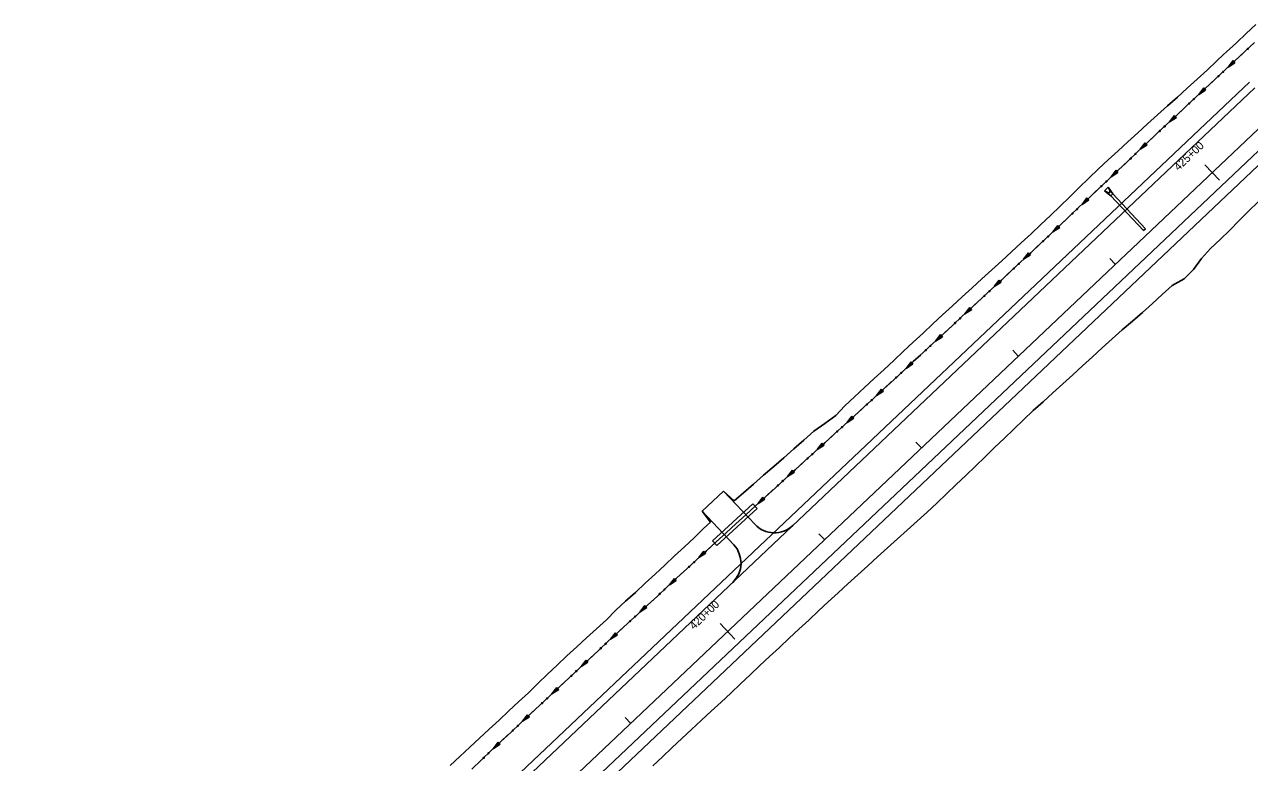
# Model space of a CAD drawing. Extents: x 1375694 to 1433473, y 1931050 to 1967991.
# Drawn here: x 1429493 to 1430411, y 1964646 to 1965198 of the extents above; entities that cross this region are included whole.
import ezdxf

# ---------------------------------------------------------------- set-up
doc = ezdxf.new("R2010")
doc.units = 0
for name, color, linetype in [('62', 7, 'Continuous'), ('R_Drainage', 7, 'Continuous'), ('R_Horz Alg', 7, 'Continuous'), ('R_Horz Alg Annot', 7, 'Continuous'), ('R_Proposed Const Limits', 7, 'Continuous'), ('R_Proposed Road', 7, 'Continuous')]:
    doc.layers.add(name, color=color, linetype=linetype)

msp = doc.modelspace()

# ---------------------------------------------------------------- linework, layer by layer
at = {"layer": '62'}
for p, q in [((1430398.79, 1965171.29), (1430395.12, 1965166.43)), ((1430400.23, 1965169.75), (1430398.79, 1965171.29)), ((1430395.12, 1965166.43), (1430400.23, 1965169.75)), ((1430376.82, 1965150.81), (1430373.16, 1965145.94)), ((1430373.16, 1965145.94), (1430378.26, 1965149.26)), ((1430378.26, 1965149.26), (1430376.82, 1965150.81)), ((1430354.87, 1965130.3), (1430351.21, 1965125.44)), ((1430351.21, 1965125.44), (1430356.31, 1965128.76)), ((1430356.31, 1965128.76), (1430354.87, 1965130.3)), ((1430332.95, 1965109.76), (1430329.32, 1965104.86)), ((1430329.32, 1965104.86), (1430334.4, 1965108.22)), ((1430334.4, 1965108.22), (1430332.95, 1965109.76)), ((1430311.13, 1965089.11), (1430307.5, 1965084.22)), ((1430312.58, 1965087.57), (1430311.13, 1965089.11)), ((1430307.5, 1965084.22), (1430312.58, 1965087.57)), ((1430289.3, 1965068.48), (1430285.67, 1965063.59)), ((1430285.67, 1965063.59), (1430290.75, 1965066.94)), ((1430290.75, 1965066.94), (1430289.3, 1965068.48)), ((1430267.48, 1965047.84), (1430263.83, 1965042.96)), ((1430263.83, 1965042.96), (1430268.93, 1965046.3)), ((1430268.93, 1965046.3), (1430267.48, 1965047.84)), ((1430245.54, 1965027.33), (1430241.87, 1965022.46)), ((1430241.87, 1965022.46), (1430246.98, 1965025.78)), ((1430246.98, 1965025.78), (1430245.54, 1965027.33)), ((1430223.57, 1965006.85), (1430219.89, 1965002)), ((1430225.01, 1965005.3), (1430223.57, 1965006.85)), ((1430219.89, 1965002), (1430225.01, 1965005.3)), ((1430201.54, 1964986.43), (1430197.86, 1964981.57)), ((1430197.86, 1964981.57), (1430202.98, 1964984.88)), ((1430202.98, 1964984.88), (1430201.54, 1964986.43)), ((1430179.51, 1964966.01), (1430175.82, 1964961.16)), ((1430175.82, 1964961.16), (1430180.95, 1964964.46)), ((1430180.95, 1964964.46), (1430179.51, 1964966.01)), ((1430157.46, 1964945.61), (1430153.77, 1964940.76)), ((1430153.77, 1964940.76), (1430158.9, 1964944.06)), ((1430158.9, 1964944.06), (1430157.46, 1964945.61)), ((1430135.37, 1964925.27), (1430131.66, 1964920.43)), ((1430131.66, 1964920.43), (1430136.8, 1964923.71)), ((1430136.8, 1964923.71), (1430135.37, 1964925.27)), ((1430113.24, 1964904.96), (1430109.51, 1964900.14)), ((1430114.67, 1964903.39), (1430113.24, 1964904.96)), ((1430109.51, 1964900.14), (1430114.67, 1964903.39)), ((1430090.99, 1964884.78), (1430087.26, 1964879.97)), ((1430087.26, 1964879.97), (1430092.41, 1964883.21)), ((1430092.41, 1964883.21), (1430090.99, 1964884.78)), ((1430068.75, 1964864.59), (1430065.02, 1964859.77)), ((1430065.02, 1964859.77), (1430070.17, 1964863.02)), ((1430070.17, 1964863.02), (1430068.75, 1964864.59)), ((1430046.53, 1964844.38), (1430042.8, 1964839.56)), ((1430042.8, 1964839.56), (1430047.95, 1964842.82)), ((1430047.95, 1964842.82), (1430046.53, 1964844.38)), ((1430002.21, 1964803.81), (1429998.52, 1964798.96)), ((1430003.64, 1964802.25), (1430002.21, 1964803.81)), ((1429998.52, 1964798.96), (1430003.64, 1964802.25)), ((1429980.14, 1964783.44), (1429976.45, 1964778.59)), ((1429976.45, 1964778.59), (1429981.57, 1964781.88)), ((1429981.57, 1964781.88), (1429980.14, 1964783.44)), ((1429958.06, 1964763.07), (1429954.36, 1964758.22)), ((1429954.36, 1964758.22), (1429959.49, 1964761.51)), ((1429959.49, 1964761.51), (1429958.06, 1964763.07)), ((1429935.96, 1964742.72), (1429932.27, 1964737.87)), ((1429932.27, 1964737.87), (1429937.4, 1964741.16)), ((1429937.4, 1964741.16), (1429935.96, 1964742.72)), ((1429913.95, 1964722.28), (1429910.28, 1964717.41)), ((1429915.39, 1964720.73), (1429913.95, 1964722.28)), ((1429910.28, 1964717.41), (1429915.39, 1964720.73)), ((1429891.99, 1964701.78), (1429888.33, 1964696.91)), ((1429888.33, 1964696.91), (1429893.44, 1964700.23)), ((1429893.44, 1964700.23), (1429891.99, 1964701.78)), ((1429870.04, 1964681.27), (1429866.38, 1964676.41)), ((1429866.38, 1964676.41), (1429871.48, 1964679.73)), ((1429871.48, 1964679.73), (1429870.04, 1964681.27)), ((1429848.09, 1964660.76), (1429844.44, 1964655.88)), ((1429844.44, 1964655.88), (1429849.54, 1964659.22)), ((1429849.54, 1964659.22), (1429848.09, 1964660.76))]:
    msp.add_line(p, q, dxfattribs=at)
for points in [[(1429828.4, 1964640.65), (1429835.65, 1964647.54), (1429842.9, 1964654.42), (1429850.18, 1964661.28), (1429857.49, 1964668.11), (1429864.8, 1964674.93), (1429872.1, 1964681.76), (1429879.41, 1964688.58), (1429886.72, 1964695.41), (1429894.03, 1964702.23), (1429901.34, 1964709.06), (1429908.65, 1964715.88), (1429915.96, 1964722.71), (1429923.27, 1964729.53), (1429930.6, 1964736.33), (1429937.95, 1964743.11), (1429945.31, 1964749.89), (1429952.67, 1964756.66), (1429960.02, 1964763.44), (1429967.38, 1964770.21), (1429974.73, 1964777), (1429982.07, 1964783.78), (1429989.42, 1964790.57), (1429996.77, 1964797.35), (1430004.12, 1964804.13), (1430011.49, 1964810.9), (1430018.86, 1964817.65), (1430026.24, 1964824.41), (1430033.61, 1964831.16), (1430040.99, 1964837.91), (1430048.39, 1964844.64), (1430055.79, 1964851.37), (1430063.19, 1964858.1), (1430070.59, 1964864.83), (1430077.99, 1964871.56), (1430085.4, 1964878.28), (1430092.81, 1964885), (1430100.22, 1964891.72), (1430107.63, 1964898.44), (1430115.04, 1964905.15), (1430122.4, 1964911.92), (1430129.77, 1964918.69), (1430137.13, 1964925.45), (1430144.49, 1964932.22), (1430151.86, 1964938.99), (1430159.2, 1964945.78), (1430166.54, 1964952.57), (1430173.88, 1964959.36), (1430181.22, 1964966.16), (1430188.56, 1964972.95), (1430195.89, 1964979.75), (1430203.23, 1964986.55), (1430210.56, 1964993.35), (1430217.89, 1965000.15), (1430225.23, 1965006.95), (1430232.54, 1965013.76), (1430239.86, 1965020.58), (1430247.17, 1965027.4), (1430254.48, 1965034.22), (1430261.8, 1965041.04), (1430269.08, 1965047.9), (1430276.35, 1965054.77), (1430283.61, 1965061.64), (1430290.88, 1965068.51), (1430298.14, 1965075.38), (1430305.41, 1965082.25), (1430312.68, 1965089.12), (1430319.94, 1965095.99), (1430327.21, 1965102.86), (1430334.47, 1965109.74), (1430341.75, 1965116.6), (1430349.05, 1965123.42), (1430356.36, 1965130.25), (1430363.67, 1965137.08), (1430370.98, 1965143.9), (1430378.28, 1965150.73), (1430385.6, 1965157.55), (1430392.91, 1965164.37), (1430398.01, 1965169.12), (1430400.26, 1965171.22), (1430407.58, 1965178.03), (1430414.9, 1965184.84)], [(1430406.1, 1965176.65), (1430400.26, 1965171.22), (1430398.01, 1965169.12), (1430395.12, 1965166.43)], [(1430406.13, 1965176.68), (1430406.1, 1965176.65)], [(1430384.12, 1965156.17), (1430378.28, 1965150.73), (1430373.16, 1965145.94)], [(1430384.15, 1965156.2), (1430384.12, 1965156.17)], [(1430362.17, 1965135.68), (1430356.36, 1965130.25), (1430351.21, 1965125.44)], [(1430362.19, 1965135.7), (1430362.17, 1965135.68)], [(1430340.22, 1965115.16), (1430334.47, 1965109.74), (1430329.32, 1965104.86)], [(1430340.25, 1965115.19), (1430340.22, 1965115.16)], [(1430318.39, 1965094.53), (1430312.68, 1965089.12), (1430307.5, 1965084.22)], [(1430318.42, 1965094.55), (1430318.39, 1965094.53)], [(1430296.57, 1965073.89), (1430290.88, 1965068.51), (1430285.67, 1965063.59)], [(1430296.59, 1965073.92), (1430296.57, 1965073.89)], [(1430274.74, 1965053.25), (1430269.08, 1965047.9), (1430263.83, 1965042.96)], [(1430274.77, 1965053.28), (1430274.74, 1965053.25)], [(1430252.84, 1965032.69), (1430247.17, 1965027.4), (1430241.87, 1965022.46)], [(1430252.87, 1965032.72), (1430252.84, 1965032.69)], [(1430230.87, 1965012.21), (1430225.23, 1965006.95), (1430219.89, 1965002)], [(1430230.9, 1965012.23), (1430230.87, 1965012.21)], [(1430208.86, 1964991.77), (1430203.23, 1964986.55), (1430197.86, 1964981.57)], [(1430208.89, 1964991.8), (1430208.86, 1964991.77)], [(1430186.83, 1964971.35), (1430181.22, 1964966.16), (1430175.82, 1964961.16)], [(1430186.86, 1964971.38), (1430186.83, 1964971.35)], [(1430164.79, 1964950.95), (1430159.2, 1964945.78), (1430153.77, 1964940.76)], [(1430164.81, 1964950.97), (1430164.79, 1964950.95)], [(1430142.71, 1964930.58), (1430137.13, 1964925.45), (1430131.66, 1964920.43)], [(1430142.74, 1964930.6), (1430142.71, 1964930.58)], [(1430120.59, 1964910.25), (1430115.04, 1964905.15), (1430109.51, 1964900.14)], [(1430120.62, 1964910.28), (1430120.59, 1964910.25)], [(1430098.37, 1964890.04), (1430092.81, 1964885), (1430087.26, 1964879.97)], [(1430098.4, 1964890.07), (1430098.37, 1964890.04)], [(1430076.12, 1964869.86), (1430070.59, 1964864.83), (1430065.02, 1964859.77)], [(1430076.15, 1964869.89), (1430076.12, 1964869.86)], [(1430053.9, 1964849.65), (1430048.39, 1964844.64), (1430042.8, 1964839.56)], [(1430053.93, 1964849.68), (1430053.9, 1964849.65)], [(1430009.55, 1964809.12), (1430004.12, 1964804.13), (1429998.52, 1964798.96)], [(1430009.58, 1964809.15), (1430009.55, 1964809.12)], [(1429987.46, 1964788.77), (1429982.07, 1964783.78), (1429976.45, 1964778.59)], [(1429987.49, 1964788.79), (1429987.47, 1964788.77)], [(1429965.4, 1964768.39), (1429960.02, 1964763.44), (1429954.36, 1964758.22)], [(1429965.43, 1964768.41), (1429965.4, 1964768.39)], [(1429943.3, 1964748.04), (1429937.95, 1964743.11), (1429932.27, 1964737.87)], [(1429943.33, 1964748.06), (1429943.3, 1964748.04)], [(1429921.25, 1964727.65), (1429915.96, 1964722.71), (1429910.28, 1964717.41)], [(1429921.27, 1964727.67), (1429921.25, 1964727.65)], [(1429899.29, 1964707.15), (1429894.03, 1964702.23), (1429888.33, 1964696.91)], [(1429899.32, 1964707.17), (1429899.29, 1964707.15)], [(1429877.34, 1964686.64), (1429872.1, 1964681.76), (1429866.38, 1964676.41)], [(1429877.37, 1964686.67), (1429877.34, 1964686.64)], [(1429855.39, 1964666.14), (1429850.18, 1964661.28), (1429844.44, 1964655.88)], [(1429855.41, 1964666.17), (1429855.39, 1964666.14)], [(1429833.56, 1964645.56), (1429833.53, 1964645.53)]]:
    msp.add_lwpolyline(points, dxfattribs=at)
for centre in [(1430409.8, 1965180.05), (1430391.48, 1965162.99), (1430387.82, 1965159.57), (1430365.86, 1965139.08), (1430369.52, 1965142.5), (1430343.91, 1965118.57), (1430347.57, 1965121.99), (1430322.07, 1965097.95), (1430325.71, 1965101.4), (1430303.89, 1965080.75), (1430300.24, 1965077.31), (1430278.42, 1965056.68), (1430282.06, 1965060.12), (1430256.54, 1965036.09), (1430260.2, 1965039.51), (1430234.57, 1965015.61), (1430238.24, 1965019.02), (1430216.24, 1964998.57), (1430212.57, 1964995.16), (1430194.21, 1964978.14), (1430190.54, 1964974.74), (1430168.5, 1964954.33), (1430172.17, 1964957.73), (1430146.43, 1964933.95), (1430150.12, 1964937.34), (1430124.31, 1964913.62), (1430128, 1964917.01), (1430105.83, 1964896.75), (1430102.11, 1964893.39), (1430079.86, 1964873.21), (1430083.57, 1964876.58), (1430057.64, 1964853), (1430061.34, 1964856.38), (1429994.86, 1964795.54), (1429991.18, 1964792.15), (1429969.11, 1964771.76), (1429972.79, 1964775.16), (1429947.02, 1964751.41), (1429950.71, 1964754.81), (1429924.95, 1964731.04), (1429928.62, 1964734.45), (1429906.65, 1964713.97), (1429902.99, 1964710.55), (1429884.69, 1964693.47), (1429881.03, 1964690.05), (1429859.08, 1964669.54), (1429862.74, 1964672.96), (1429837.2, 1964648.96), (1429840.83, 1964652.41)]:
    msp.add_circle(centre, 0.375, dxfattribs=at)
at = {"layer": 'R_Drainage'}
for p, q in [((1430305.27, 1965076.61), (1430302.35, 1965073.87)), ((1430307.26, 1965070.09), (1430302.35, 1965073.87)), ((1430302.35, 1965073.87), (1430304.92, 1965072.44)), ((1430308.73, 1965071.45), (1430305.27, 1965076.61)), ((1430305.27, 1965076.61), (1430306.54, 1965073.95)), ((1430308.73, 1965071.45), (1430307.26, 1965070.09)), ((1430308.73, 1965071.45), (1430307.26, 1965070.09)), ((1430307.26, 1965070.09), (1430331.71, 1965043.96)), ((1430333.16, 1965045.35), (1430308.73, 1965071.45)), ((1430331.71, 1965043.96), (1430333.16, 1965045.35)), ((1430038.9, 1964839.22), (1430008.81, 1964811.66)), ((1430012.02, 1964808.16), (1430042.1, 1964835.71)), ((1430042.1, 1964835.71), (1430038.9, 1964839.22)), ((1430008.81, 1964811.66), (1430012.02, 1964808.16))]:
    msp.add_line(p, q, dxfattribs=at)
msp.add_arc((1430305.49, 1965073.45), 1.17, 240.6309, 25.57105, dxfattribs=at)
at = {"layer": 'R_Horz Alg'}
msp.add_line((1429279.02, 1964042.46), (1430431.75, 1965133.47), dxfattribs=at)
at = {"layer": 'R_Horz Alg Annot'}
for points in [[(1430377.62, 1965093.25), (1430388.61, 1965081.62)], [(1430306.36, 1965023.05), (1430310.49, 1965018.7)], [(1430233.74, 1964954.31), (1430237.86, 1964949.96)], [(1430161.11, 1964885.57), (1430165.23, 1964881.22)], [(1430088.48, 1964816.83), (1430092.6, 1964812.48)], [(1430014.48, 1964749.55), (1430025.47, 1964737.93)], [(1429943.22, 1964679.35), (1429947.35, 1964675)]]:
    msp.add_lwpolyline(points, dxfattribs=at)
at = {"layer": 'R_Proposed Const Limits'}
for p, q in [((1430017.04, 1964848.67), (1430024.95, 1964841.62)), ((1430000.89, 1964833.73), (1430007.31, 1964825.64))]:
    msp.add_line(p, q, dxfattribs=at)
for points in [[(1430024.95, 1964841.62), (1430031.87, 1964847.55), (1430039.42, 1964854.12), (1430046.94, 1964860.72), (1430054.54, 1964867.24), (1430062.09, 1964873.81), (1430069.66, 1964880.36), (1430077.22, 1964886.91), (1430084.67, 1964893.6), (1430092.83, 1964899.52), (1430101.04, 1964905.4), (1430107.88, 1964912.72), (1430115.17, 1964919.56), (1430122.55, 1964926.32), (1430129.87, 1964933.12), (1430137.23, 1964939.89), (1430144.58, 1964946.68), (1430151.87, 1964953.52), (1430159.17, 1964960.35), (1430166.47, 1964967.19), (1430173.75, 1964974.05), (1430181.14, 1964980.79), (1430188.52, 1964987.54), (1430195.9, 1964994.29), (1430203.28, 1965001.04), (1430210.66, 1965007.79), (1430218.04, 1965014.53), (1430225.41, 1965021.3), (1430232.77, 1965028.07), (1430240.13, 1965034.84), (1430247.45, 1965041.65), (1430254.78, 1965048.45), (1430262, 1965055.38), (1430269.25, 1965062.27), (1430276.43, 1965069.23), (1430283.61, 1965076.19), (1430290.78, 1965083.16), (1430297.91, 1965090.18), (1430305.23, 1965096.99), (1430312.6, 1965103.75), (1430320.01, 1965110.47), (1430327.42, 1965117.19), (1430334.8, 1965123.94), (1430342.2, 1965130.66), (1430349.64, 1965137.36), (1430357.08, 1965144.03), (1430364.49, 1965150.76), (1430371.88, 1965157.49), (1430379.3, 1965164.2), (1430386.62, 1965171.02), (1430391.71, 1965175.78), (1430393.96, 1965177.88), (1430401.28, 1965184.7), (1430408.59, 1965191.51), (1430415.9, 1965198.34)], [(1429963.91, 1964642.95), (1429971.19, 1964649.81), (1429978.47, 1964656.66), (1429985.74, 1964663.52), (1429993.05, 1964670.35), (1430000.39, 1964677.14), (1430007.74, 1964683.93), (1430015.08, 1964690.72), (1430022.42, 1964697.51), (1430029.7, 1964704.36), (1430036.97, 1964711.23), (1430044.26, 1964718.08), (1430051.51, 1964724.97), (1430058.83, 1964731.78), (1430066.09, 1964738.66), (1430073.42, 1964745.46), (1430080.78, 1964752.23), (1430088.11, 1964759.04), (1430095.43, 1964765.84), (1430102.78, 1964772.62), (1430110.19, 1964779.35), (1430117.6, 1964786.07), (1430125, 1964792.79), (1430132.4, 1964799.53), (1430139.8, 1964806.25), (1430147.23, 1964812.95), (1430154.67, 1964819.64), (1430162.09, 1964826.35), (1430169.49, 1964833.07), (1430176.8, 1964839.9), (1430184.03, 1964846.8), (1430191.26, 1964853.71), (1430198.49, 1964860.62), (1430205.72, 1964867.53), (1430212.94, 1964874.45), (1430220.13, 1964881.4), (1430227.33, 1964888.34), (1430234.51, 1964895.3), (1430241.7, 1964902.25), (1430249.01, 1964909.08), (1430256.43, 1964915.79), (1430263.84, 1964922.5), (1430271.26, 1964929.21), (1430278.63, 1964935.98), (1430286.05, 1964942.68), (1430293.41, 1964949.46), (1430300.79, 1964956.2), (1430308.18, 1964962.94), (1430315.68, 1964969.57), (1430323.34, 1964976.02), (1430330.94, 1964982.54), (1430338.36, 1964989.24), (1430345.73, 1964996.01), (1430353.15, 1965002.72), (1430362.13, 1965007.78), (1430369.25, 1965014.8), (1430375.15, 1965023.11), (1430381.98, 1965030.44), (1430389.18, 1965037.39), (1430396.33, 1965044.38), (1430403.39, 1965051.46), (1430410.49, 1965058.51), (1430417.61, 1965065.54)], [(1429812.19, 1964643.23), (1429819.46, 1964650.1), (1429826.76, 1964656.93), (1429834.07, 1964663.76), (1429841.39, 1964670.57), (1429848.75, 1964677.34), (1429856.1, 1964684.12), (1429863.39, 1964690.97), (1429870.69, 1964697.8), (1429877.89, 1964704.74), (1429885.16, 1964711.61), (1429892.4, 1964718.5), (1429899.56, 1964725.49), (1429906.92, 1964732.25), (1429914.39, 1964738.91), (1429921.84, 1964745.59), (1429929.27, 1964752.29), (1429936.15, 1964759.57), (1429943.56, 1964766.28), (1429950.98, 1964772.99), (1429958.35, 1964779.75), (1429965.65, 1964786.58), (1429972.92, 1964793.45), (1429980.29, 1964800.22), (1429987.59, 1964807.05), (1429994.86, 1964813.91), (1430002.06, 1964820.85), (1430007.31, 1964825.64)]]:
    msp.add_lwpolyline(points, dxfattribs=at)
at = {"layer": 'R_Proposed Road'}
for p, q in [((1429258.4, 1964064.25), (1430411.13, 1965155.26)), ((1429262.53, 1964059.89), (1430415.26, 1965150.9)), ((1429287.27, 1964033.74), (1430440, 1965124.75)), ((1429292.77, 1964027.93), (1430445.5, 1965118.94)), ((1430000.89, 1964833.73), (1430017.04, 1964848.67)), ((1430017.04, 1964848.67), (1430040.57, 1964823.81)), ((1430000.89, 1964833.73), (1430024.59, 1964808.69))]:
    msp.add_line(p, q, dxfattribs=at)
for centre, start, end in [((1430055.09, 1964837.56), 223.42441, 313.42441), ((1430010.07, 1964794.94), 313.42441, 43.42441)]:
    msp.add_arc(centre, 20, start, end, dxfattribs=at)

# ---------------------------------------------------------------- texts
at = {"layer": 'R_Horz Alg Annot'}
for s, p in [('425+00', (1430357.93, 1965088.38)), ('420+00', (1429994.79, 1964744.68))]:
    msp.add_text(s, height=6, rotation=43.42441, dxfattribs=at).set_placement(p)

doc.saveas('drawing.dxf')
